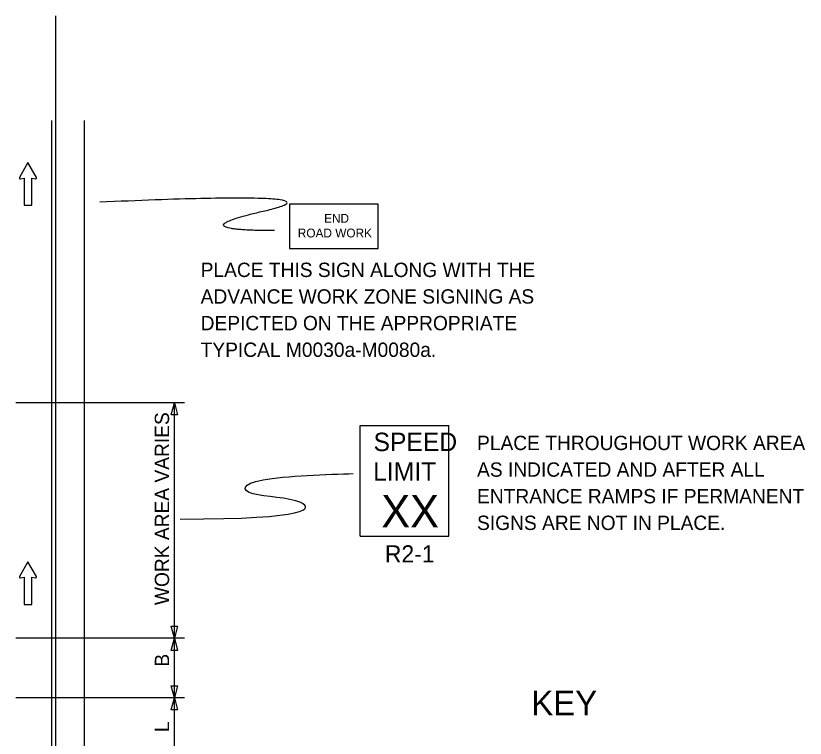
# Model space of a CAD drawing. Extents: x 16745 to 18475, y 6983 to 8234.
# Drawn here: x 17008.7 to 17394, y 7881.8 to 8234.5 of the extents above; entities that cross this region are included whole.
import ezdxf

# ---------------------------------------------------------------- set-up
doc = ezdxf.new("R2010")
doc.units = 0
for name, color, linetype in [('ALI_LEGAL_EX', 7, 'Continuous'), ('MT_SCRATCH_LEVEL_E', 7, 'Continuous'), ('PAVT_EDGE_EX', 7, 'Continuous'), ('TRAFFIC_SIGNS_PR', 7, 'Continuous'), ('TYPICAL_TEXT_DIMEN_EX', 7, 'Continuous'), ('TYPICAL_TEXT_DIMEN_PR', 7, 'Continuous')]:
    doc.layers.add(name, color=color, linetype=linetype)

msp = doc.modelspace()

# ---------------------------------------------------------------- linework, layer by layer
at = {"layer": 'ALI_LEGAL_EX'}
msp.add_line((17028.11, 8234.45), (17028.11, 7405.27), dxfattribs=at)
msp.add_line((17028.11, 8234.45), (17028.11, 7405.27), dxfattribs=at)
at = {"layer": 'MT_SCRATCH_LEVEL_E'}
for p, q in [((17014.65, 8162.8), (17010.54, 8155.56)), ((17018.8, 8155.56), (17014.65, 8162.8)), ((17011.03, 8154.87), (17012.8, 8155.19)), ((17012.8, 8155.19), (17012.8, 8141.93)), ((17016.54, 8141.93), (17016.54, 8155.19)), ((17016.54, 8155.19), (17018.32, 8154.87)), ((17012.8, 8141.93), (17016.54, 8141.93)), ((17014.65, 7967.94), (17010.54, 7960.7)), ((17018.8, 7960.7), (17014.65, 7967.94)), ((17011.03, 7960.01), (17012.8, 7960.33)), ((17012.8, 7960.33), (17012.8, 7947.07)), ((17016.54, 7947.07), (17016.54, 7960.33)), ((17016.54, 7960.33), (17018.32, 7960.01)), ((17012.8, 7947.07), (17016.54, 7947.07))]:
    msp.add_line(p, q, dxfattribs=at)
for centre, start, end in [((17010.95, 8155.33), 150.4248, 279.9638), ((17018.39, 8155.33), 260.0362, 29.7731), ((17010.95, 7960.47), 150.4248, 279.9638), ((17018.39, 7960.47), 260.0362, 29.7731)]:
    msp.add_arc(centre, 0.463, start, end, dxfattribs=at)
at = {"layer": 'PAVT_EDGE_EX'}
for p, q in [((17026.13, 8183.26), (17026.13, 7404.46)), ((17042.13, 8183.26), (17042.13, 7404.46))]:
    msp.add_line(p, q, dxfattribs=at)
at = {"layer": 'TRAFFIC_SIGNS_PR'}
for p, q in [((17176.86, 8034.47), (17220.06, 8034.47)), ((17176.86, 7980.47), (17176.86, 8034.47)), ((17220.06, 7980.47), (17220.06, 8034.47)), ((17176.86, 7980.47), (17220.06, 7980.47))]:
    msp.add_line(p, q, dxfattribs=at)
msp.add_lwpolyline([(17142.33, 8120.91), (17185.53, 8120.91), (17185.53, 8142.51), (17142.33, 8142.51)], close=True, dxfattribs=at)
for points, degree in [([(17135, 8129.59), (17087.77, 8129.59), (17172.79, 8148.94), (17049.69, 8143.45)], 2), ([(17089.03, 7988.75), (17153.61, 7988.75), (17153.61, 7999.51), (17118.7, 7999.51), (17118.7, 8009.17), (17161.56, 8010.69), (17173.47, 8010.95)], 3)]:
    msp.add_open_spline(points, degree=degree, dxfattribs=at)
at = {"layer": 'TYPICAL_TEXT_DIMEN_PR'}
for p, q in [((17091.13, 8045.46), (17008.73, 8045.46)), ((17084.56, 8039.6), (17086.13, 8045.46)), ((17086.13, 7930.55), (17086.13, 8045.46)), ((17086.13, 8045.46), (17087.7, 8039.6)), ((17086.13, 8039.6), (17084.56, 8039.6)), ((17087.7, 8039.6), (17086.13, 8039.6)), ((17086.13, 7930.55), (17084.56, 7936.41)), ((17084.56, 7936.41), (17086.13, 7936.41)), ((17086.13, 7936.41), (17087.7, 7936.41)), ((17087.7, 7936.41), (17086.13, 7930.55)), ((17091.13, 7930.55), (17008.73, 7930.55)), ((17084.56, 7924.69), (17086.13, 7930.55)), ((17086.13, 7901.49), (17086.13, 7930.55)), ((17086.13, 7930.55), (17087.7, 7924.69)), ((17086.13, 7924.69), (17084.56, 7924.69)), ((17087.7, 7924.69), (17086.13, 7924.69)), ((17086.13, 7901.49), (17084.56, 7907.36)), ((17084.56, 7907.36), (17086.13, 7907.36)), ((17086.13, 7907.36), (17087.7, 7907.36)), ((17087.7, 7907.36), (17086.13, 7901.49)), ((17091.13, 7901.49), (17008.73, 7901.49)), ((17084.56, 7895.63), (17086.13, 7901.49)), ((17086.13, 7870.93), (17086.13, 7901.49)), ((17086.13, 7901.49), (17087.7, 7895.63)), ((17086.13, 7895.63), (17084.56, 7895.63)), ((17087.7, 7895.63), (17086.13, 7895.63))]:
    msp.add_line(p, q, dxfattribs=at)
msp.add_open_spline([(17210.78, 7973.47), (17210.8, 7973.47), (17210.8, 7973.47), (17210.8, 7973.47)], degree=2, dxfattribs=at)

# ---------------------------------------------------------------- texts
at = {"layer": 'TRAFFIC_SIGNS_PR'}
for s, height, p in [('END', 4.31, (17159.21, 8133.43)), ('ROAD WORK', 4.31, (17146.39, 8126.25)), ('PLACE THIS SIGN ALONG WITH THE', 7, (17098.95, 8106.93)), ('ADVANCE WORK ZONE SIGNING AS', 7, (17098.95, 8093.93)), ('DEPICTED ON THE APPROPRIATE', 7, (17098.95, 8080.93)), ('TYPICAL M0030a-M0080a.', 7, (17098.95, 8067.93)), ('SPEED', 9, (17183.34, 8021.94)), ('PLACE THROUGHOUT WORK AREA', 7, (17233.85, 8022.44)), ('LIMIT', 9, (17183.16, 8007.54)), ('AS INDICATED AND AFTER ALL', 7, (17233.85, 8009.44)), ('ENTRANCE RAMPS IF PERMANENT', 7, (17233.85, 7996.44)), ('XX', 15.785, (17187.11, 7984.7)), ('SIGNS ARE NOT IN PLACE.', 7, (17233.85, 7983.44)), ('R2-1', 8.37, (17188.87, 7967.6))]:
    msp.add_text(s, height=height, dxfattribs=at).set_placement(p)
at = {"layer": 'TYPICAL_TEXT_DIMEN_EX'}
msp.add_text('KEY', height=12, dxfattribs=at).set_placement((17260.36, 7892.98))
at = {"layer": 'TYPICAL_TEXT_DIMEN_PR'}
for s, p in [('WORK AREA VARIES', (17083.57, 7946.77)), ('B', (17083.57, 7916.76)), ('L', (17083.57, 7884.79))]:
    msp.add_text(s, height=7, rotation=90, dxfattribs=at).set_placement(p)

doc.saveas('drawing.dxf')
